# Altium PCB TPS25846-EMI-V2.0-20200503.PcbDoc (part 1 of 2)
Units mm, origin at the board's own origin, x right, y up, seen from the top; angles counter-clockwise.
Board outline 35.01 x 50.01 mm, 4 copper layers (Top Layer, Signal Layer 1, Signal Layer 2, Bottom Layer), stack 2.155 mm thick; 63 components, 30 nets, 189 pads, 82 vias.
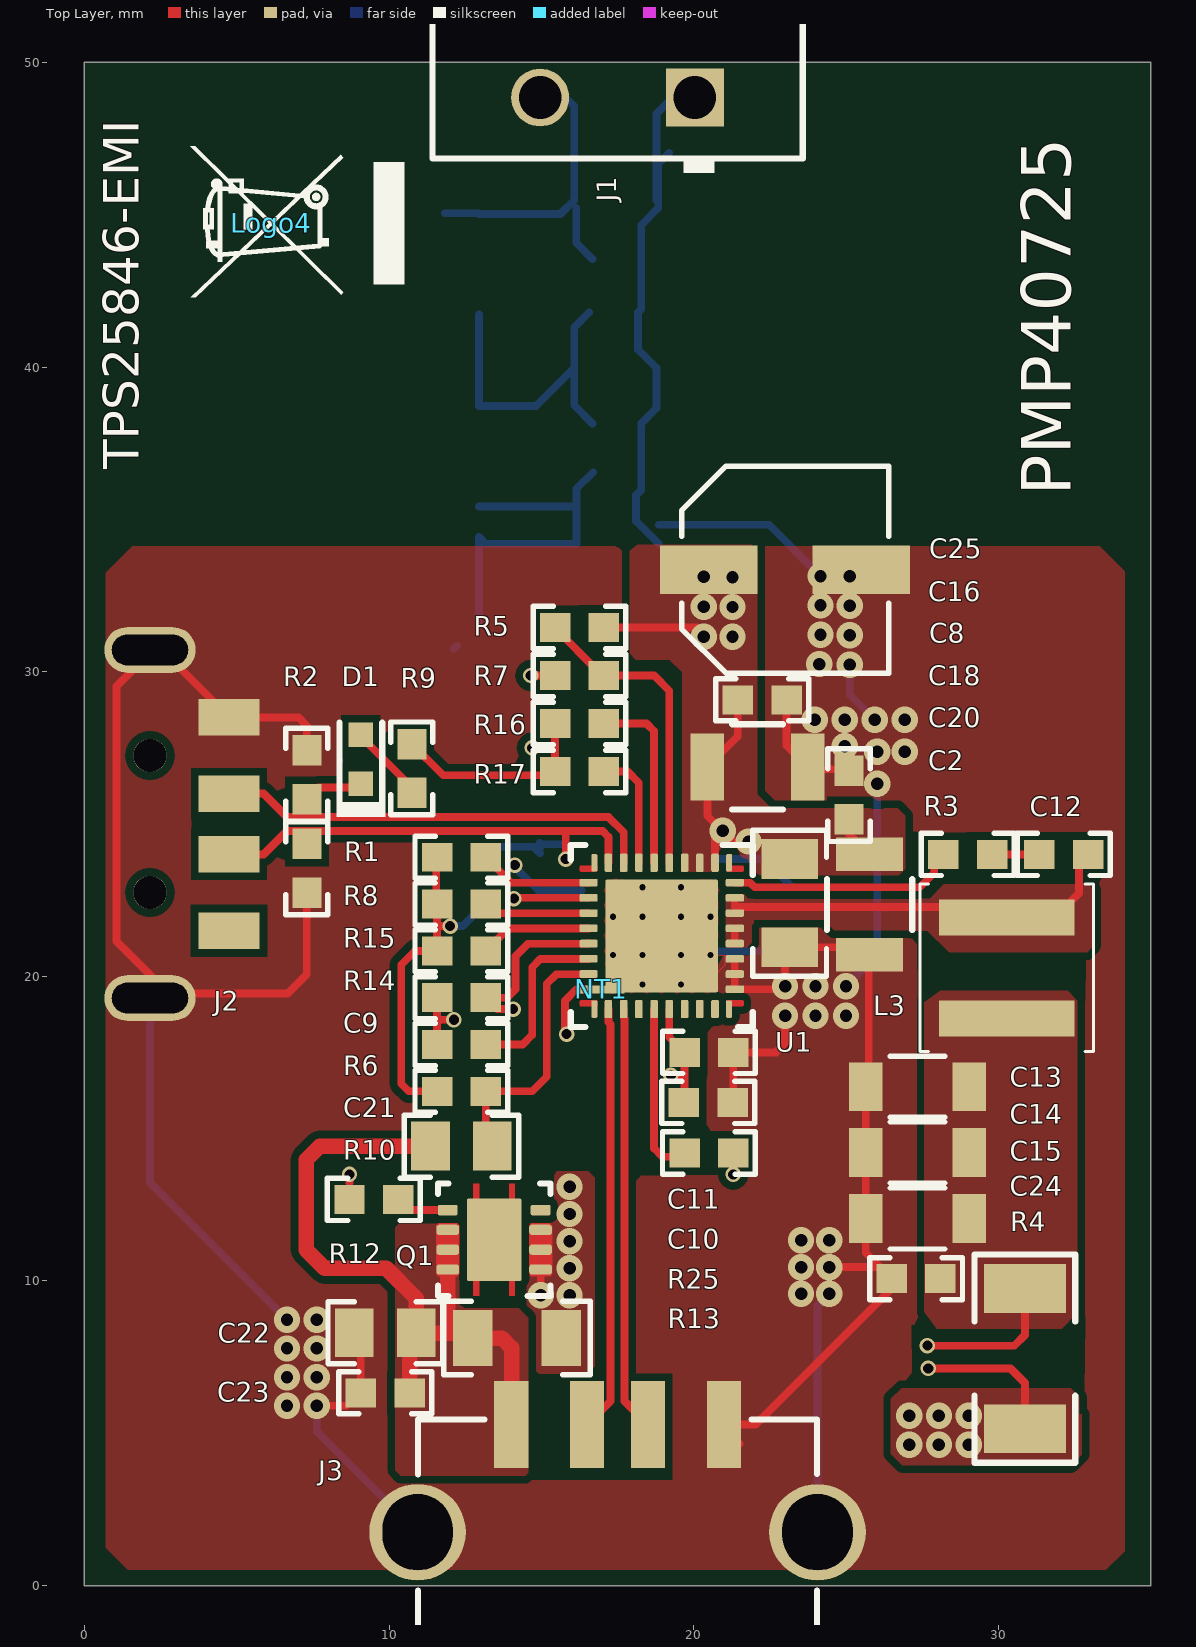
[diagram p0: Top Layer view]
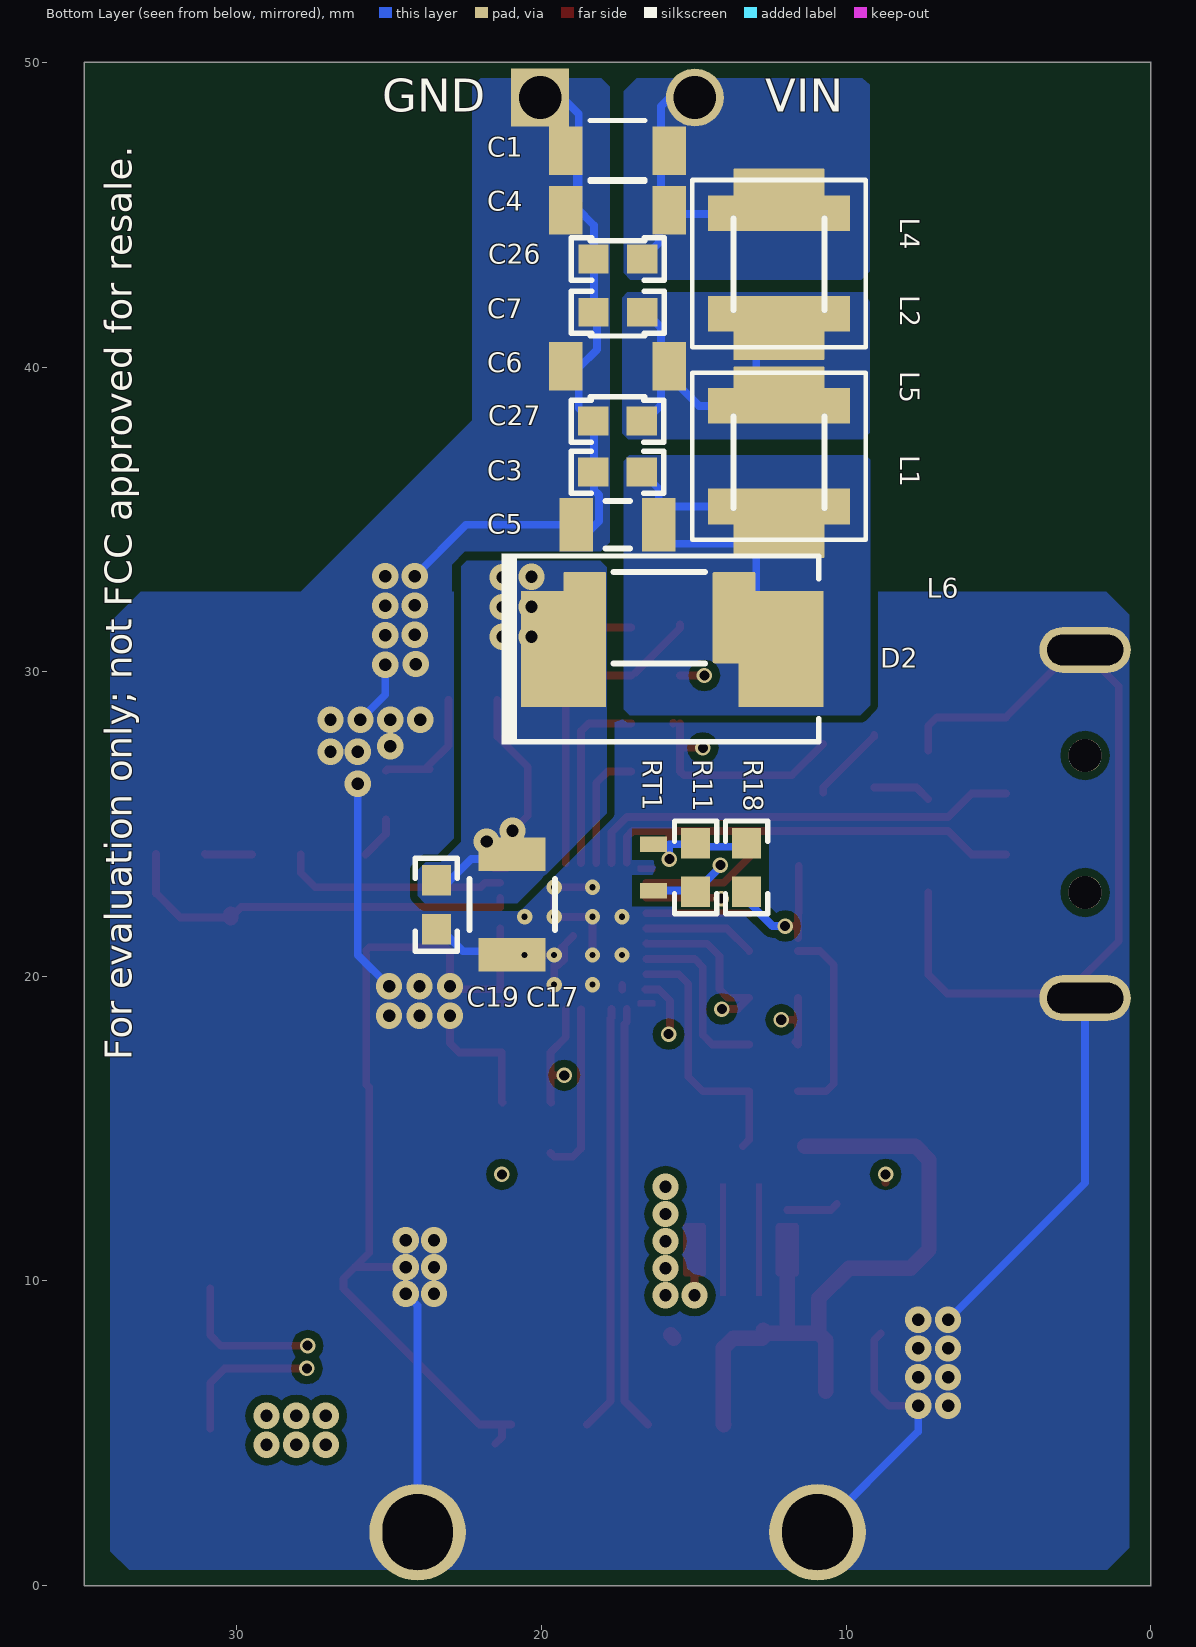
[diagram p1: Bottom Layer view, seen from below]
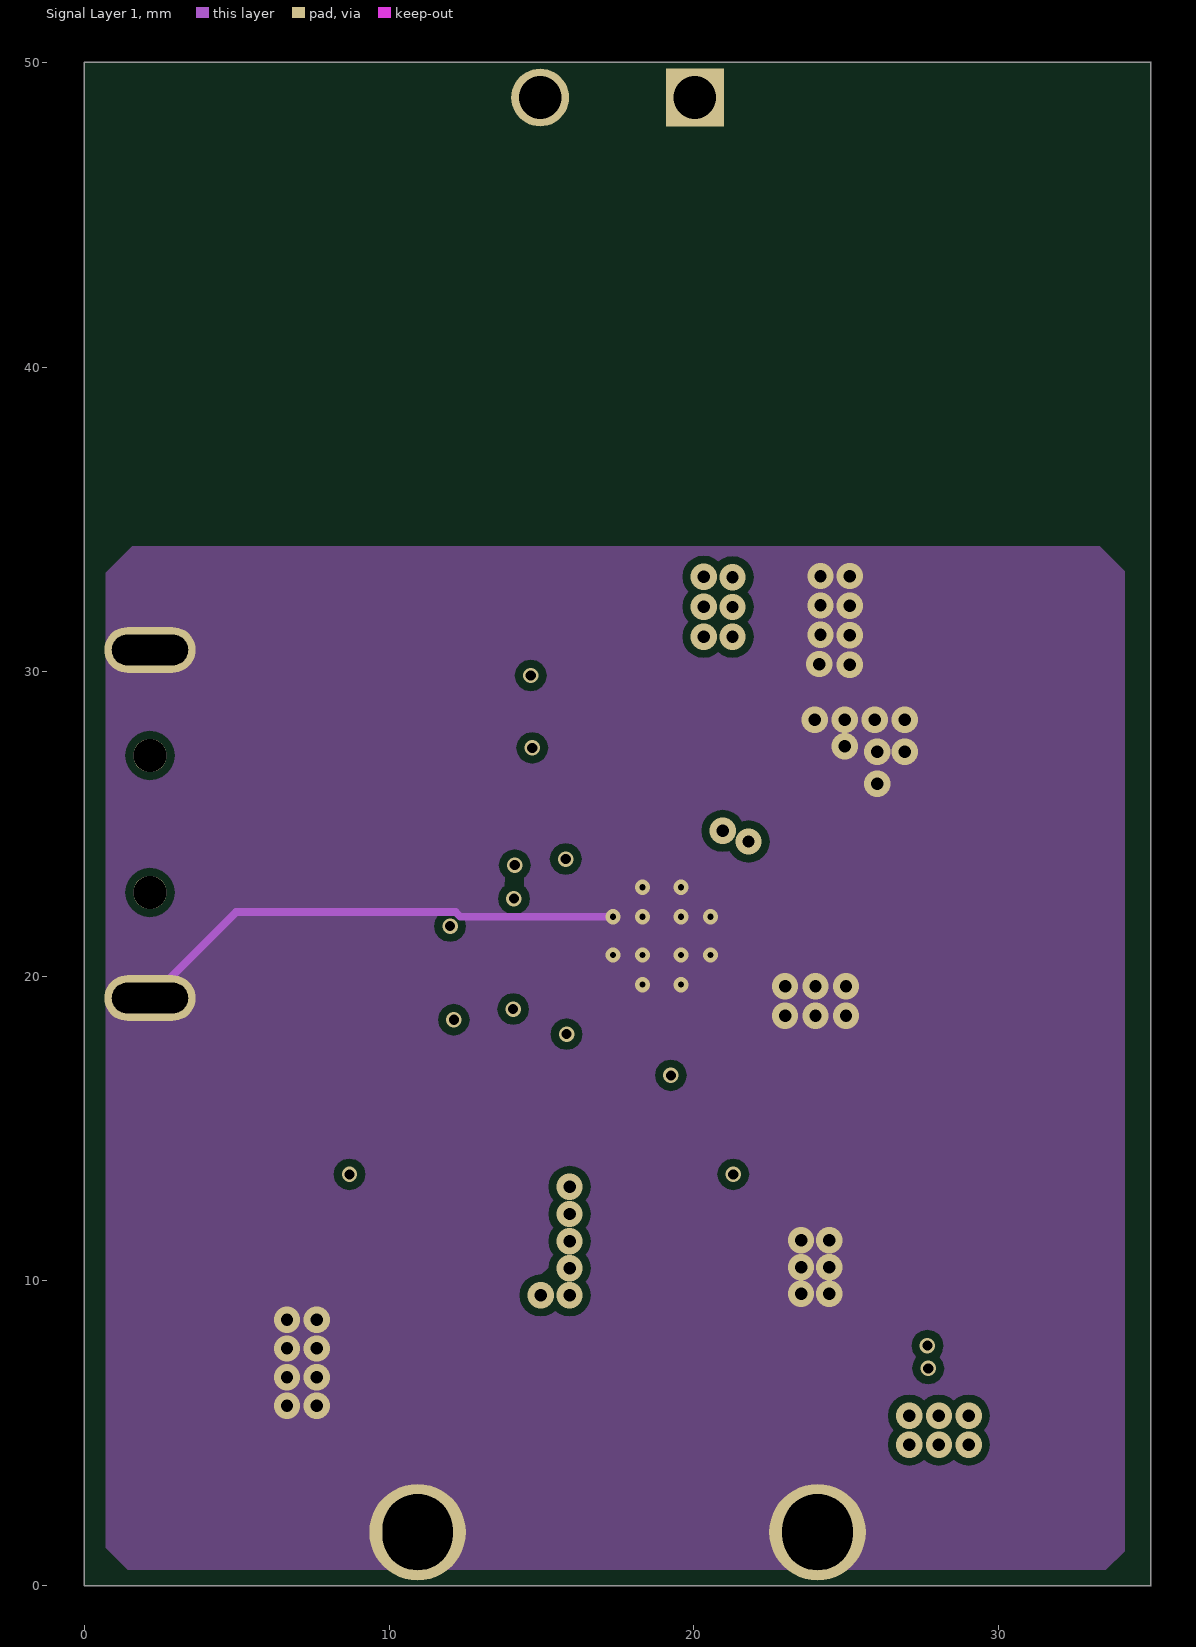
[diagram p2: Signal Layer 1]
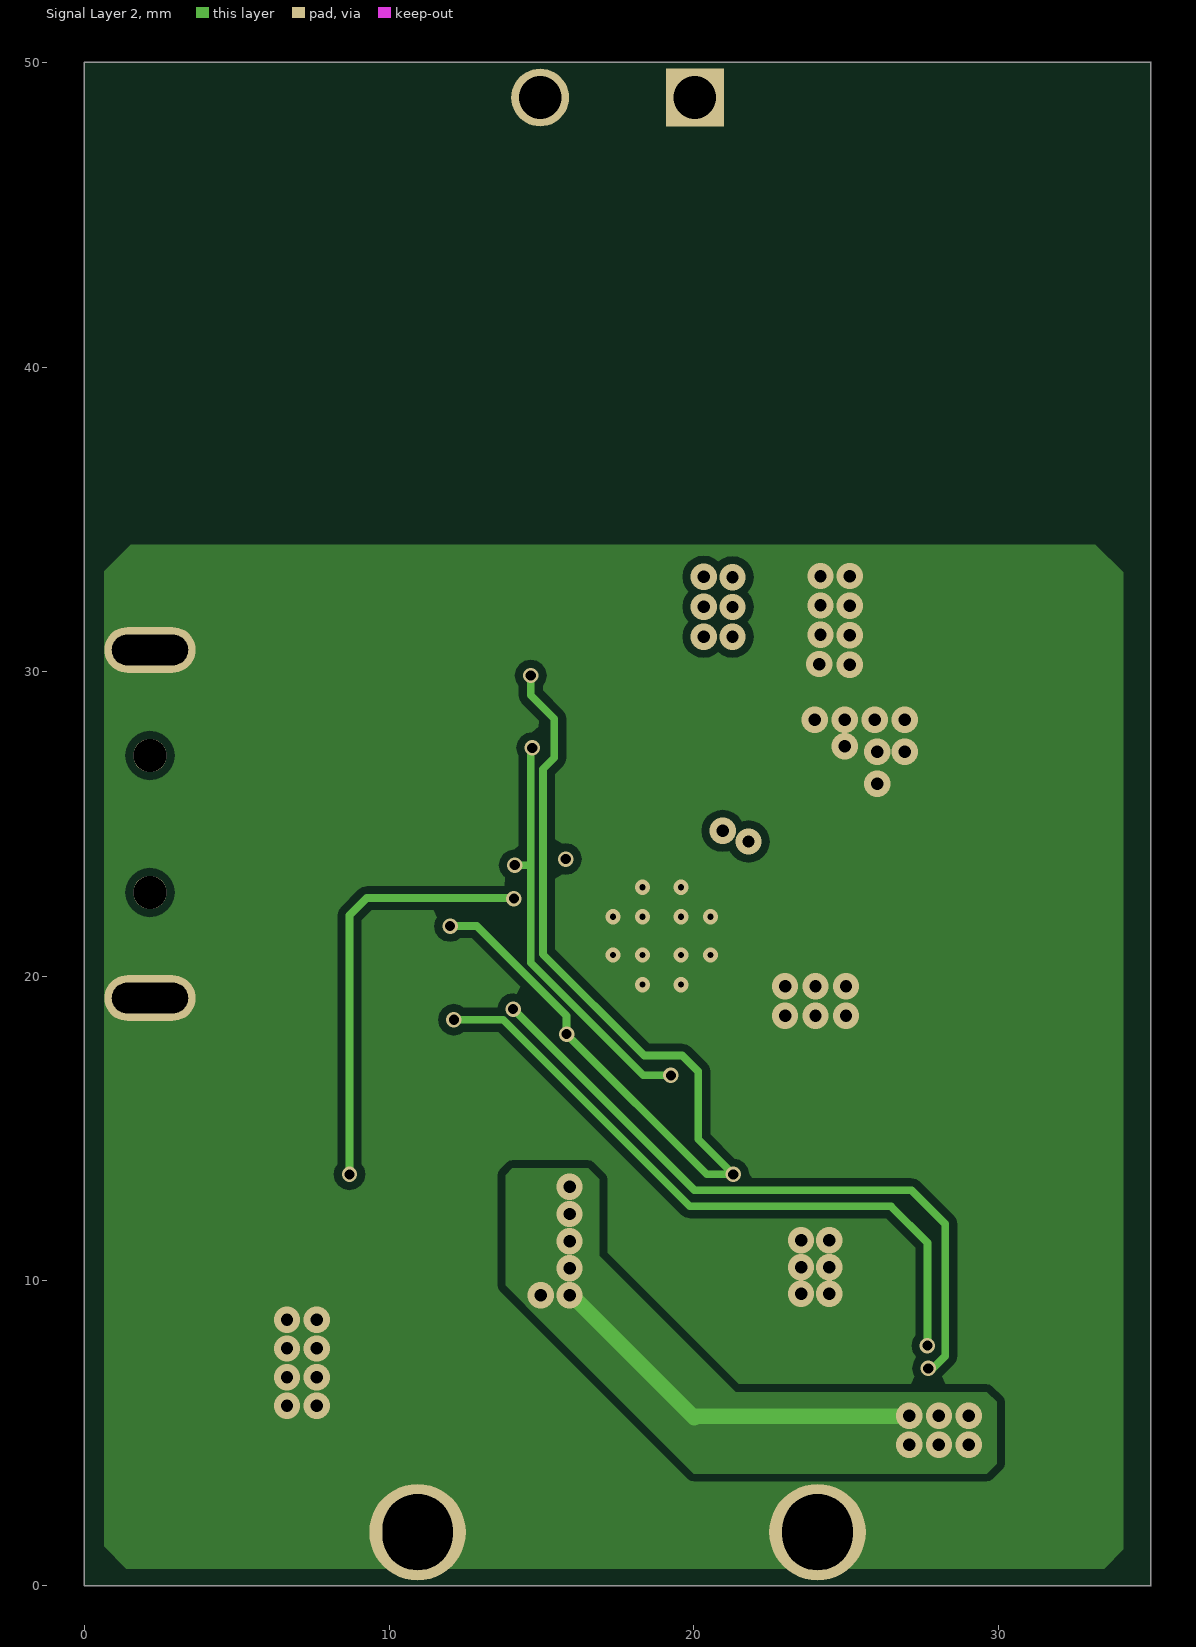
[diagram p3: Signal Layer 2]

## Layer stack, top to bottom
Top Solder: solder mask 0.0102, Solder Resist, Dk 3.5
Top Layer: signal copper 0.0356
Dielectric1: core 1.5037, FR-4, Dk 4.8
Signal Layer 1: signal copper 0.036
Dielectric 2: dielectric 0.254, Dk 4.2
Signal Layer 2: signal copper 0.036
Dielectric 3: dielectric 0.254, Dk 4.2
Bottom Layer: signal copper 0.0356
Bottom Solder: solder mask 0.0102, Solder Resist, Dk 3.5

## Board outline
-0.005,0 ccw(c0,0) 0,-0.005 35,-0.005 ccw(c35,0) 35.005,0 35.005,50 ccw(c35,50) 35,50.005 0,50.005 ccw(c0,50) -0.005,50

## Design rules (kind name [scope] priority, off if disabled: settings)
AcuteAngle [All] p1: minimum=4.50000000000000E+0001 checktracksonly=FALSE
AssemblyTestPointUsage [All] p1: valid=2
BoardOutlineClearance BoardOutlineClearance_1 [ispad and InComponent('J3')] p1: gap=0.508 ignorepadtopadclearanceinfootprint=FALSE
BoardOutlineClearance BoardOutlineClearance_MountingHoles [OnCopper and InComponentClass('Mounting Holes')] p2: gap=0.508 ignorepadtopadclearanceinfootprint=FALSE
BoardOutlineClearance BoardOutlineClearance_Poly [OnCopper and IsPoly] p3: gap=0.508 ignorepadtopadclearanceinfootprint=FALSE
BoardOutlineClearance [OnCopper and Not InComponentClass('Logo') and not InComponentClass('FiducialMark') and not InRegion(1000,500,4000,800) and not InPoly] p4: gap=0.508 ignorepadtopadclearanceinfootprint=FALSE
Clearance Clearance_3 [InComponent('NT1')] p1: gap=0.076 ignorepadtopadclearanceinfootprint=FALSE
Clearance Clearance_2 [isPad or IsArc vs IsKeepOut] p2: gap=0.254 ignorepadtopadclearanceinfootprint=FALSE
Clearance Clearance_1 [InPolygon AND (INNet(VIN) OR InNet('SW')OR InNet('SENS')OR InNet('VBUS1')OR InNet('VBUS2'))] p3: gap=0.254 ignorepadtopadclearanceinfootprint=FALSE
Clearance Clearance_Keepouts [((IsTrack Or IsArc) And Not InPoly) And IsFree and IsKeepOut vs ((IsTrack Or IsArc) And Not InPoly) And IsFree and IsKeepOut] p4: gap=0.254 ignorepadtopadclearanceinfootprint=FALSE
Clearance Clearance_Poly [InPolygon] p5: gap=0.254 ignorepadtopadclearanceinfootprint=FALSE
Clearance [All] p6: gap=0.076 ignorepadtopadclearanceinfootprint=FALSE
ComponentClearance ComponentClearance_1 [InComponent('U1') vs InComponent('NT1')] p1: gap=0 collisioncheckmode=3 verticalgap=0 showdistances=FALSE
ComponentClearance ComponentClearance_MountingHoles_FiducialMarks [InComponentClass('Mounting Holes') vs InComponentClass('FiducialMark')] p2: gap=1.27 collisioncheckmode=3 verticalgap=0.254 showdistances=FALSE
ComponentClearance ComponentClearance_Shunt [InComponentClass('Header') vs InComponentClass('Shunt')] p3: gap=0 collisioncheckmode=3 verticalgap=0 showdistances=FALSE
ComponentClearance ComponentClearance_Logo [InComponentClass('Logo')] p4: gap=1.27 collisioncheckmode=3 verticalgap=0.254 showdistances=FALSE
ComponentClearance ComponentClearance_ScrewToNut [(HasFootprint('NY PMS 440 0025 PH')) vs (HasFootprint('Keystone_1902C'))] p5: gap=0.127 collisioncheckmode=3 verticalgap=0.254 showdistances=FALSE
ComponentClearance ComponentClearance_MountingHoles [InComponentClass('Mounting Holes')] p6: gap=6.35 collisioncheckmode=3 verticalgap=2540 showdistances=FALSE
ComponentClearance ComponentClearance_SmallPassives [HasFootprint('0201*') or HasFootprint('0402*') or HasFootprint('0508') or HasFootprint('0603*') or HasFootprint('0612') or HasFootprint('0805*') or HasFootprint('0815*') or HasFootprint('0830*') or HasFootprint('1206*') or HasFootprint('1210*') or HasFootprint('1808*') or HasFootprint('1812*') or HasFootprint('1825*') or HasFootprint('2010*') or HasFootprint('2220*') or HasFootprint('2225*') or HasFootprint('2512*') or HasFootprint('2728*') or HasFootprint('3518*') vs HasFootprint('0201*') or HasFootprint('0402*') or HasFootprint('0508') or HasFootprint('0603*') or HasFootprint('0612') or HasFootprint('0805*') or HasFootprint('0815*') or HasFootprint('0830*') or HasFootprint('1206*') or HasFootprint('1210*') or HasFootprint('1808*') or HasFootprint('1812*') or HasFootprint('1825*') or HasFootprint('2010*') or HasFootprint('2220*') or HasFootprint('2225*') or HasFootprint('2512*') or HasFootprint('2728*') or HasFootprint('3518*')] p7: gap=0.38 collisioncheckmode=3 verticalgap=0.254 showdistances=FALSE
ComponentClearance ComponentClearance_THtoSMT [IsThruComponent vs IsSMTComponent] p8: gap=0.762 collisioncheckmode=3 verticalgap=0.762 showdistances=FALSE
ComponentClearance ComponentClearance_THtoTH [IsThruComponent vs IsThruComponent] p9: gap=0.762 collisioncheckmode=3 verticalgap=0.762 showdistances=FALSE
ComponentClearance [All] p10 off: gap=0.762 collisioncheckmode=3 verticalgap=0.254 showdistances=FALSE
DiffPairsRouting [InDifferentialPairClass('All Differential Pairs')] p1: maxlimit=0.254 minlimit=0.127 mostfreqgap=0.203 toplayer_minwidth=0.127 toplayer_maxwidth=0.254 toplayer_prefwidth=0.203 midlayer1_minwidth=0.127 midlayer1_maxwidth=0.254 midlayer1_prefwidth=0.203 midlayer2_minwidth=0.127 midlayer2_maxwidth=0.254 midlayer2_prefwidth=0.203 bottomlayer_minwidth=0.127 bottomlayer_maxwidth=0.254 bottomlayer_prefwidth=0.203 maxuncoupledlength=254
FabricationTestPointUsage TestPointUsage [All] p1: valid=2 allowmultiple=FALSE
FabricationTestpoint Testpoint [All] p1: side=3 testpointundercomponent=TRUE minsize=1.016 maxsize=2.54 preferedsize=1.524 minholesize=0 maxholesize=1.016 preferedholesize=0.813 testpointgrid=0.025 allowsidetop=TRUE allowsidebottom=TRUE usegrid=TRUE gridtolerance=0
FanoutControl Fanout_LCC [IsLCC] p1: bgadir=Out bgaviamode=Centered fanoutstyle=Auto fanoutdirection=Alternating viagrid=0.025 // Fanout_LCC (Default Rule)
FanoutControl Fanout_BGA [IsBGA] p2: bgadir=Out bgaviamode=Centered fanoutstyle=Auto fanoutdirection=Alternating viagrid=0.025 // Fanout_BGA (Default Rule)
FanoutControl Fanout_Default [All] p4: bgadir=Out bgaviamode=Centered fanoutstyle=Auto fanoutdirection=Alternating viagrid=0.025 // Fanout_Default (Default Rule)
FanoutControl Fanout_Small [(CompPinCount < 5)] p5: bgadir=Out bgaviamode=Centered fanoutstyle=Auto fanoutdirection=OutThenIn viagrid=0.025 // Fanout_Small (Default Rule)
HoleSize [All] p1: absolutevalues=TRUE maxlimit=6.375 minlimit=0.152 maxpercent=80.000 minpercent=20.000
HoleToHoleClearance [All] p1: gap=0.152 allowstackedmicrovias=TRUE
MinimumAnnularRing MinimumAnnularRing_ThermalPadVias [IsPad] p1: minimumring=0.051
MinimumAnnularRing [All] p2: minimumring=0.076
MinimumSolderMaskSliver MinimumSolderMaskSliver_Logo [InComponentClass('Logo') vs InComponentClass('Logo')] p1: minsoldermaskwidth=0.025
MinimumSolderMaskSliver [All] p2: minsoldermaskwidth=0
PlaneConnect [All] p1: planeconnectstyle=Direct reliefexpansion=0.254 reliefentries=4 reliefconductorwidth=0.254 reliefairgap=0.254
PolygonConnect [All] p1: connectstyle=Direct reliefconductorwidth=0.254 reliefentries=4 polygonreliefangle="90 Angle" airgapwidth=0.254
RoutingVias ThermalPadVias [IsVia and InAnyComponent] p1: holewidth=0.2 width=0.33 viastyle="Through Hole" minholewidth=0.198 minwidth=0.33 maxholewidth=0.33 maxwidth=0.381
RoutingVias [All] p2: holewidth=0.254 width=0.33 viastyle="Through Hole" minholewidth=0.152 minwidth=0.254 maxholewidth=0.33 maxwidth=0.508
ShortCircuit ShortCircuit_1 [ispad and InComponent('U1')] p1: allowed=TRUE
ShortCircuit [All] p2: allowed=FALSE
SilkToBoardRegionClearance [Not ((IsComment or IsDesignator) And (Hide <> 'False')) and not InRegion(1000,500,4000,800)] p1:
SilkToSilkClearance SilkToSilkClearance_Pb-FreeLogo [(HasFootprint('Pb-Free_Overlay_Medium') OR HasFootprint('Pb-Free_Overlay_Small')) vs (HasFootprint('Pb-Free_Overlay_Medium') OR HasFootprint('Pb-Free_Overlay_Small'))] p1: silktosilkclearance=0
SilkToSilkClearance [All] p2: silktosilkclearance=0
SilkToSolderMaskClearance [IsPad] p1: minsilkscreentomaskgap=0 clearancetoexposedcopper=TRUE
SilkToSolderMaskClearance SilkToComponentPadClearance [(IsPad or IsFill or IsRegion) and InAnycomponent] p2: minsilkscreentomaskgap=0 clearancetoexposedcopper=TRUE
SolderMaskExpansion [All] p1: expansion=0.05
Width [All] p1: maxlimit=2.54 minlimit=0.152 preferedwidth=0.254 midlayer1_minwidth=0.178 midlayer2_minwidth=0.178 bottomlayer_minwidth=0.178 minimp=50.000000 maximp=50.000000 favimp=50.000000 checkconnectedcopper=TRUE
13 further rules are at their usual default settings.

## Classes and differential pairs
component class TPS25846-EMI-V2.0: !PCB Logo3 Logo4
differential pair DATA_OUT: +DATA_OUT_P -DATA_OUT_N
differential pair DATA_IN: +DATA_IN_P -DATA_IN_N

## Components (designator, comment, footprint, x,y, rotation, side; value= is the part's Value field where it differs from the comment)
C1 "CGA5L1X7R1H106K160AC" 1206_190 17.5,47.1 r0 bottom value=10uF
C2 "UMJ325KB7106MMHP" 1210_280 25.775,22.35 r270 top value=10uF
C3 "C0603X332K5RACTU" 0603 17.5,36.55 r0 bottom value=3300pF
C4 "UMJ316AB7225KLHT" 1206_180 17.5,45.15 r0 bottom value=2.2uF
C5 "GRM31CR71H475KA12L" 1206_180L 17.5,34.825 r0 bottom value=4.7uF
C6 "UMJ316AB7225KLHT" 1206_180 17.5,40.025 r0 bottom value=2.2uF
C7 "C0603X332K5RACTU" 0603 17.49,41.8 r0 bottom value=3300pF
C8 "GRM1885C1H222JA01D" 0603 22.25,29.075 r0 top value=2200pF
C9 "C0603C104K5RACAUTO" 0603 12.375,19.299 r180 top value=0.1uF
C10 "885012106018" 0603 20.475,15.858 r0 top value=2.2uF
C11 "C0603C104K5RACAUTO" 0603 20.5,17.5 r0 top value=0.1uF
C12 "C0603C104K5RACAUTO" 0603 32.15,24 r0 top value=0.1uF
C13 "GCM31CR71A226KE02" 1206_180 27.35,16.375 r180 top value=22uF
C14 "GCM31CR71A226KE02" 1206_180 27.35,14.212 r180 top value=22uF
C15 "GCM31CR71A226KE02" 1206_180 27.35,12.05 r180 top value=22uF
C16 "C0603C104K5RACAUTO" 0603 25.1,25.95 r90 top value=0.1uF
C17 "UMJ325KB7106MMHP" 1210_280 20.959,22.35 r270 bottom value=10uF
C18 "UMJ325KB7106MMHP" 1210_280 22.1,26.875 r0 top value=10uF
C19 "C0603C104K5RACAUTO" 0603 23.45,22.35 r270 bottom value=0.1uF
C20 "C1206C104M5RACTU" 1206 23.15,22.4 r270 top value=0.1uF
C21 "CL10B224KO8VPNC" 0603 12.375,16.225 r180 top value=0.22uF
C22 "08055C105KAT2A" 0805_HV 9.875,8.3 r180 top value=1uF
C23 "C0603C104K5RACAUTO" 0603 9.875,6.325 r180 top value=0.1uF
C24 "GRM1885C1H222JA01D" 0603 27.3,10.075 r180 top value=2200pF
C25 "EEE-FK1H220P" SM_RADIAL_D 23,33.35 r0 top value=22uF
C26 "GRM188R71H222KA01D" 0603 17.49,43.55 r0 bottom value=2200pF
C27 "GRM188R71H222KA01D" 0603 17.5,38.225 r0 bottom value=2200pF
D1 "150060RS75000" WL-SMCW_RED 9.075,27.125 r90 top value=NC
D2 "B540C-13-F" SMC 15.7,30.75 r180 bottom value=40V
J1 "1757242" PHOENIX_1757242 17.5,52.85 r180 top locked
J2 "48037-1000" CONN_USB-A-48037-1000 2.5,25 r180 top locked
J3 "896-43-004-00-000000" CONN_USB_896-43-004-00-000000 17.5,3.517 r0 top locked
L1 "74279252" 1812_170_HighSpeed 12.2,36.875 r270 bottom value="880 ohm"
L2 "NC" 1812_170_HighSpeed 12.2,43.375 r270 bottom value="880 ohm"
L3 "XAL5050-822MEB" XAL5050 30.275,20.275 r270 top value=8.2uH
L4 "XAL5030-102MEB" XAL5030 12.2,43.4 r270 bottom value=1uH
L5 "XAL5030-102MEB" XAL5030 12.2,37.075 r270 bottom value=1uH
L6 "NC" 1812_170_HighSpeed 16.125,31.775 r0 bottom value="880 ohm"
Logo3 "FCC disclaimer" FCC_disclaimer -9.05,95.425 r90 top
Logo4 "WEEE logo" WEEE_Minimum 6.125,44.721 r90 top
NT1 "Net-Tie" Net-Tie_10milWide_30milLong 16.966,19.57 r180 top net-tie
Q1 "CSD85312Q3E" DPA0008A 13.45,11.35 r180 top value=20V
R1 "CRCW060349K9FKEA" 0603 12.375,23.907 r0 top value=49.9k
R2 "CRCW060315K0JNEA" 0603 7.3,26.616 r270 top value=15k
R3 "MCT06030C2008FP500" 0603 29,24 r0 top value=2.00
R4 "WSL2010R0150FEA" 2010 30.875,7.45 r270 top value=0.015
R5 "CRCW060320K0JNEA" 0603 16.25,31.45 r0 top value=20k
R6 "CRCW0603301RFKEA" 0603 12.375,17.762 r180 top value=301
R7 "CR0603-FX-4991ELF" 0603 16.25,29.874 r0 top value=4.99k
R8 "CRCW060315K0JNEA" 0603 7.3,23.55 r90 top value=15k
R9 "CRCW060310K0JNEA" 0603 10.747,26.825 r90 top value=10k
R10 "ERJ-6GEYJ101V" 0805_HV 12.375,14.425 r180 top value=100
R11 "CRCW06031K00FKEA" 0603 14.94,23.575 r270 bottom value=1.00k
R12 "RMCF0603ZT0R00" 0603 9.5,12.675 r0 top value=0
R13 "RC1206JR-070RL" 1206 14.2,8.125 r0 top value=0
R14 "CRCW06035K62FKEA" 0603 12.375,20.834 r0 top value=5.62k
R15 "CR0603-FX-4991ELF" 0603 12.375,22.372 r180 top value=4.99k
R16 "CRCW0603100KFKEA" 0603 16.25,28.301 r180 top value=100k
R17 "CRCW0603100KFKEA" 0603 16.25,26.725 r180 top value=100k
R18 "CRCW060339K2FKEA" 0603 13.264,23.575 r90 bottom value=39.2k
R25 "CRCW06035K10JNEA" 0603 20.5,14.2 r180 top value=5.1k
RT1 "NCP18WM474J03RB" 0603S 16.325,23.575 r270 bottom value=NC
U1 "TPS25840QWRHBTQ1" RHB0032R 18.95,21.325 r270 top

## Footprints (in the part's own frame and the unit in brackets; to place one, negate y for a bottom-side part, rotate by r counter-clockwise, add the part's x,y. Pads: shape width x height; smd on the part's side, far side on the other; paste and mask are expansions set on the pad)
0603 [mm] "0603 from SM-752 data"
  rect 1x0.95 smd: 1(-0.8,0) 2(0.8,0)
  silkscreen extent -1.52,-0.69 1.52,0.69, body extent -0.87,-0.47 0.87,0.47, height 1
0603S [mil]
  rect 20x35 smd: 1(-30,0) 2(30,0)
  body extent -34,-19 34,19, height 39
0805_HV [mil] "0805 with 30mil clearance between pads"
  rect 50x63 smd: 1(-40,0) 2(40,0)
  silkscreen extent -74,-40 74,40, body extent -43,-29 43,29, height 57
1206 [mm] "1206 from SM-752 data"
  rect 1.3x1.85 smd: 1(-1.45,0) 2(1.45,0)
  silkscreen extent -2.4,-1.21 2.4,1.21, body extent -1.7,-0.9 1.7,0.9, height 1.35
1206_180 [mm] "1206_180"
  rect 1.1x1.6 smd: 1(-1.7,0) 2(1.7,0)
  silkscreen extent -0.9,-1 0.9,1, body extent -1.75,-0.95 1.75,0.95, height 1.8
1206_180L [mm] "1206_180"
  rect 1.1x1.75 smd: 1(-1.35,0) 2(1.35,0)
  silkscreen extent -0.4,-0.77 0.4,0.77, body extent -1.75,-0.95 1.75,0.95, height 1.8
1206_190 [mm] "1206_190"
  rect 1.1x1.6 smd: 1(-1.7,0) 2(1.7,0)
  silkscreen extent -0.9,-1 0.9,1, body extent -1.75,-0.95 1.75,0.95, height 1.9
1210_280 [mm] "SMD, 2-Leads, Body 3.6x2.8mm, Height 2.8mm"
  rect 1.1x2.2 smd: 1(-1.65,0) 2(1.65,0)
  silkscreen extent -0.84,-1.4 0.84,1.4, body extent -1.8,-1.4 1.8,1.4, height 2.8
1812_170_HighSpeed [mm] "Wurth recommended land pattern"
  rrect7% 1.4x3 smd: 1(-2.45,0) 2(2.45,0)
  silkscreen extent -1.5,-1.5 1.5,1.5, body extent -2.25,-1.6 2.25,1.6, height 1.51
2010 [mm] "Chip Capacitor, Body 5.08x2.54mm, IPC Medium Density"
  rect 1.6x2.7 smd: 1(-2.3,0) 2(2.3,0)
  silkscreen extent -3.42,-1.65 3.42,1.65, body extent -2.73,-1.45 2.73,1.45, height 1.66
CONN_USB-A-48037-1000 [mm] "Molex"
  rect 2x1.2 smd: 1(-2.25,3.5) 2(-2.25,1) 3(-2.25,-1) 4(-2.25,-3.5)
  oval 3x1.5 hole 1 slot 2.5 at 0 deg: 5(0.35,5.715) 6(0.35,-5.715)
  round 1.092 hole 1.092 unplated: 7(0.35,2.248) 8(0.35,-2.248)
  body extent -3.13,-6.35 18.15,6.35, height 3.09
CONN_USB_896-43-004-00-000000 [mm] "MILLMAX"
  rect 1.12x2.87 smd: 1(-3.49,1.768) 2(-1,1.768) 3(1,1.768) 4(3.49,1.768)
  round 3.17 hole 2.3 slot 2.5 at 90 deg: 5(-6.565,-1.767) 6(6.565,-1.767)
  silkscreen extent -6.55,-10.54 6.55,1.93, body extent -6.55,-12.07 6.55,1.92, height 6.99
DPA0008A [mm] "SON, 8-Leads, Body 3.3x3.3mm, Pitch 0.65mm"
  rrect59% 0.75x0.34 smd paste-0.2 mask-0.2: 1(-1.525,0.975) 2(-1.525,0.325) 3(-1.525,-0.325) 6(1.525,-0.325) 7(1.525,0.325) 8(1.525,0.975)
  rrect29% 0.65x0.34 smd: 4(-1.525,-0.975) 5(1.525,-0.975)
  rrect50% 0.2x0.3 on Top Paste: 9(-0.59,1.7) 9(-0.59,-1.7) 9(0.59,1.7) 9(0.59,-1.7)
  rrect8% 1.63x1.19 on Top Paste: 9(0,0.695) 9(0,-0.695)
  rrect6% 1.8x2.7 smd paste-1: 9(0,0)
  Top Layer region: 0.49,-1.85 0.69,-1.85 0.69,1.85 0.49,1.85
  Top Layer region: -0.49,1.85 -0.69,1.85 -0.69,-1.85 -0.49,-1.85
  Top Layer region: -1.9,-0.44 -1.9,1.1 -1.892,1.138 -1.871,1.171 -1.838,1.192 -1.8,1.2 -1.8,1.2 -1.25,1.2 -1.212,1.192 -1.179,1.171 -1.158,1.138 -1.15,1.1 -1.15,1.1 -1.15,-0.44 -1.158,-0.478 -1.179,-0.511 -1.212,-0.532 -1.25,-0.54 -1.25,-0.54 -1.8,-0.54 -1.838,-0.532 -1.871,-0.511 -1.892,-0.478 -1.9,-0.44
  Top Layer region: 1.9,-0.44 1.9,1.1 1.892,1.138 1.871,1.171 1.838,1.192 1.8,1.2 1.8,1.2 1.25,1.2 1.212,1.192 1.179,1.171 1.158,1.138 1.15,1.1 1.15,1.1 1.15,-0.44 1.158,-0.478 1.179,-0.511 1.212,-0.532 1.25,-0.54 1.25,-0.54 1.8,-0.54 1.838,-0.532 1.871,-0.511 1.892,-0.478 1.9,-0.44
  silkscreen extent -1.85,-1.85 1.85,1.85, body extent -1.7,-1.7 1.7,1.7, height 1.01
FCC_disclaimer [mm]
Net-Tie_10milWide_30milLong [mil] "10mil net tie, no solder mask opening, no solder paste"
  rect 30x10 smd paste-5 mask-5: 1(-15,0) 2(15,0)
PHOENIX_1757242 [mm] "Header, 5.08 mm, 2x1, R/A, TH"
  rect 1.9x1.9 hole 1.4: 1(-2.54,4)
  round 1.9 hole 1.4: 2(2.54,4)
  silkscreen extent -6.08,-6 6.08,6.47, body extent -6.05,-5.93 6.1,6.08, height 8.6
RHB0032R [mm] "QFN, 32-Leads, Body 5x5mm, Pitch 0.5mm, Thermal Pad 3.7x3.7mm"
  rrect40% 0.6x0.25 smd: 1(-2.4,1.75) 2(-2.4,1.25) 3(-2.4,0.75) 4(-2.4,0.25) 5(-2.4,-0.25) 6(-2.4,-0.75) 7(-2.4,-1.25) 8(-2.4,-1.75) 17(2.4,-1.75) 18(2.4,-1.25) 19(2.4,-0.75) 20(2.4,-0.25) 21(2.4,0.25) 22(2.4,0.75) 23(2.4,1.25) 24(2.4,1.75)
  rrect40% 0.25x0.6 smd: 9(-1.75,-2.4) 10(-1.25,-2.4) 11(-0.75,-2.4) 12(-0.25,-2.4) 13(0.25,-2.4) 14(0.75,-2.4) 15(1.25,-2.4) 16(1.75,-2.4) 25(1.75,2.4) 26(1.25,2.4) 27(0.75,2.4) 28(0.25,2.4) 29(-0.25,2.4) 30(-0.75,2.4) 31(-1.25,2.4) 32(-1.75,2.4)
  rrect9% 1.06x1.06 on Top Paste: 33(-1.26,1.26) 33(-1.26,0) 33(-1.26,-1.26) 33(0,1.26) 33(0,0) 33(0,-1.26) 33(1.26,1.26) 33(1.26,0) 33(1.26,-1.26)
  rrect3% 3.7x3.7 smd paste-2: 33(0,0)
  rrect50% 0.575x0.2 smd: A1(-2.4,2.213) A2(-2.4,-2.213) A3(2.4,-2.213) A4(2.4,2.213)
  Top Layer region: 2.113,2.638 2.113,2.163 2.116,2.143 2.127,2.127 2.143,2.116 2.163,2.113 2.163,2.113 2.262,2.113 2.282,2.116 2.298,2.127 2.309,2.143 2.312,2.163 2.312,2.163 2.312,2.638 2.309,2.657 2.298,2.673 2.282,2.684 2.262,2.688 2.262,2.688 2.163,2.688 2.143,2.684 2.127,2.673 2.116,2.657 2.113,2.638
  Top Layer region: -2.113,2.638 -2.113,2.163 -2.116,2.143 -2.127,2.127 -2.143,2.116 -2.163,2.113 -2.163,2.113 -2.262,2.113 -2.282,2.116 -2.298,2.127 -2.309,2.143 -2.312,2.163 -2.312,2.163 -2.312,2.638 -2.309,2.657 -2.298,2.673 -2.282,2.684 -2.262,2.688 -2.262,2.688 -2.163,2.688 -2.143,2.684 -2.127,2.673 -2.116,2.657 -2.113,2.638
  Top Layer region: -2.113,-2.638 -2.113,-2.163 -2.116,-2.143 -2.127,-2.127 -2.143,-2.116 -2.163,-2.113 -2.163,-2.113 -2.262,-2.113 -2.282,-2.116 -2.298,-2.127 -2.309,-2.143 -2.312,-2.163 -2.312,-2.163 -2.312,-2.638 -2.309,-2.657 -2.298,-2.673 -2.282,-2.684 -2.262,-2.688 -2.262,-2.688 -2.163,-2.688 -2.143,-2.684 -2.127,-2.673 -2.116,-2.657 -2.113,-2.638
  Top Layer region: 2.113,-2.638 2.113,-2.163 2.116,-2.143 2.127,-2.127 2.143,-2.116 2.163,-2.113 2.163,-2.113 2.262,-2.113 2.282,-2.116 2.298,-2.127 2.309,-2.143 2.312,-2.163 2.312,-2.163 2.312,-2.638 2.309,-2.657 2.298,-2.673 2.282,-2.684 2.262,-2.688 2.262,-2.688 2.163,-2.688 2.143,-2.684 2.127,-2.673 2.116,-2.657 2.113,-2.638
  silkscreen extent -2.99,-2.99 2.99,2.99, body extent -2.5,-2.5 2.5,2.5, height 1
SM_RADIAL_D [mm] "6.3 x 5.8mm:  Panasonic D"
  rect 3.2x1.6 smd: 1(-2.5,0) 2(2.5,0)
  silkscreen extent -3.4,-3.4 3.4,3.4, body extent -3.4,-3.4 3.4,3.4, height 6.1
SMC [mil] "Molded Diode, 2-Leads, Body 6.9x5.8mm, IPC Medium Density, based on OnSemi component dimensions and land patterns"
  rect 110x150 smd: 1(-140.49,0) 2(140.49,0)
  silkscreen extent -221,-123 189,124, body extent -156,-116 156,116, height 91
WEEE_Minimum [mm] "WEEElie bin"
  silkscreen extent -2.42,-4.38 2.52,2.65
WL-SMCW_RED [mm] "WURTH"
  rect 0.8x0.8 smd: 1(-0.8,0) 2(0.8,0)
  silkscreen extent -1.9,-0.8 1.2,0.8, body extent -0.85,-0.45 0.85,0.45, height 0.8
XAL5030 [mil] "Coilcraft XAL5030 12/12/11"
  rect 46x183 smd: 1(-65,0) 2(65,0)
  silkscreen extent -108,-112 108,112, body extent -108,-112 108,112, height 122
XAL5050 [mm] "CoilCraft XAL5050 5.28 x 5.48 x 5.1 mm"
  rect 1.18x4.44 smd: 1(-1.655,0) 2(1.655,0)
  silkscreen extent -2.75,-2.85 2.75,2.85, body extent -2.74,-2.84 2.74,2.84, height 5.1

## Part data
C1: library part CMP-0085950-1, "CAP, CERM, 10 µF, 50 V,+/- 10%, X7R, AEC-Q200 Grade 1, 1206", Cap_Case=1206, Manufacturer=TDK, TempCo=X7R, Tolerance_%=10%, Value2=50V, ValueDisplayed=10µF
C2 C18: library part CMP-0082302-1, "CAP, CERM, 10 µF, 50 V,+/- 20%, X7R, AEC-Q200 Grade 1, 1210", Cap_Case=1210, Manufacturer="Taiyo Yuden", Supplier Part Number 1=587-6027-1-ND, TempCo=X7R, Tolerance_%=20%, Value2=50V, ValueDisplayed=10µF
C3 C7: library part CMP-0006985-4, "CAP, CERM, 3300 pF, 50 V, +/- 10%, X7R, 0603", Cap_Case=0603, Manufacturer=Kemet, Supplier Part Number 1=399-5339-1-ND, TempCo=X7R, Tolerance_%=10%, Value1=Unknown, Value2=50V, ValueDisplayed=3300pF
C4 C6: library part CMP-0080745-1, "CAP, CERM, 2.2 µF, 50 V,+/- 10%, X7R, AEC-Q200 Grade 1, 1206", Cap_Case=1206, Manufacturer="Taiyo Yuden", Supplier Part Number 1=587-4271-1-ND, TempCo=X7R, Tolerance_%=10%, Value2=50V, ValueDisplayed=2.2µF
C5: library part CMP-0008969-2, "CAP, CERM, 4.7 uF, 50 V, +/- 10%, X7R, 1206", Cap_Case=2220, Manufacturer=MuRata, Supplier Part Number 1=24R6347, TempCo=X7R, Tolerance_%=10%, Value1=Unknown, Value2=50V, ValueDisplayed=NC
C8: library part CMP-0007198-4, "CAP, CERM, 2200 pF, 50 V, +/- 5%, C0G/NP0, 0603", Cap_Case=0603, Manufacturer=MuRata, Supplier Part Number 1=490-1459-1-ND, TempCo=C0G/NP0, Tolerance_%=5%, Value1=Unknown, Value2=50V, ValueDisplayed=NC
C9 C11 C12 C16 C23: library part CMP-0079602-1, "CAP, CERM, 0.1 µF, 50 V,+/- 10%, X7R, AEC-Q200 Grade 1, 0603", Cap_Case=0603, Manufacturer=Kemet, Supplier Part Number 1=399-6856-1-ND, TempCo=X7R, Tolerance_%=10%, Value2=50V, ValueDisplayed=0.1µF
C10: library part CMP-0006825-5, "CAP, CERM, 2.2 uF, 16 V, +/- 20%, X5R, 0603", Cap_Case=0603, Manufacturer="Wurth Elektronik", Supplier Part Number 1=732-7915-1-ND, TempCo=X5R, Tolerance_%=20%, Value1=Unknown, Value2=16V, ValueDisplayed=2.2uF
C13 C14 C15: library part CMP-0008811-2, "CAP, CERM, 22 uF, 10 V, +/- 10%, X7R, AEC-Q200 Grade 1, 1206", Cap_Case=1206, Manufacturer=MuRata, TempCo=X7R, Tolerance_%=10%, Value1=Unknown, Value2=10V, ValueDisplayed=22uF
C17: library part CMP-0082302-1, "CAP, CERM, 10 µF, 50 V,+/- 20%, X7R, AEC-Q200 Grade 1, 1210", Cap_Case=1210, Manufacturer="Taiyo Yuden", Supplier Part Number 1=587-6027-1-ND, TempCo=X7R, Tolerance_%=20%, Value2=50V, ValueDisplayed=NC
C19: library part CMP-0079602-1, "CAP, CERM, 0.1 µF, 50 V,+/- 10%, X7R, AEC-Q200 Grade 1, 0603", Cap_Case=0603, Manufacturer=Kemet, Supplier Part Number 1=399-6856-1-ND, TempCo=X7R, Tolerance_%=10%, Value2=50V, ValueDisplayed=NC
C20: library part CMP-0008587-2, "CAP, CERM, 0.1 uF, 50 V, +/- 20%, X7R, 1206", Cap_Case=1206, Manufacturer=Kemet, Supplier Part Number 1=399-1248-1-ND, TempCo=X7R, Tolerance_%=20%, Value1="0.059 ohm", Value2=50V, ValueDisplayed=0.1uF
C21: library part CMP-0080102-1, "CAP, CERM, 0.22 µF, 16 V,+/- 10%, X7R, AEC-Q200 Grade 1, 0603", Cap_Case=0603, Manufacturer=Samsung, Supplier Part Number 1=1276-6868-1-ND, TempCo=X7R, Tolerance_%=10%, Value2=16V, ValueDisplayed=0.22µF
C22: library part CMP-0007634-2, "CAP, CERM, 1 uF, 50 V, +/- 10%, X7R, 0805", Cap_Case=0805, Manufacturer=AVX, Supplier Part Number 1=478-7956-1-ND, TempCo=X7R, Tolerance_%=10%, Value1=Unknown, Value2=50V, ValueDisplayed=1uF
C24: library part CMP-0007198-4, "CAP, CERM, 2200 pF, 50 V, +/- 5%, C0G/NP0, 0603", Cap_Case=0603, Manufacturer=MuRata, Supplier Part Number 1=490-1459-1-ND, TempCo=C0G/NP0, Tolerance_%=5%, Value1=Unknown, Value2=50V, ValueDisplayed=2200pF
C25: library part CMP-0011179-2, "CAP, AL, 22 uF, 50 V, +/- 20%, 0.88 ohm, AEC-Q200 Grade 2, SMD", Cap_Case=D, Manufacturer=Panasonic, Supplier Part Number 1=PCE3811CT-ND, Tolerance_%=20%, Value1="0.88 ohm", Value2=50V, ValueDisplayed=22uF
C26 C27: library part CMP-0007443-4, "CAP, CERM, 2200 pF, 50 V, +/- 10%, X7R, 0603", Cap_Case=0603, Manufacturer=MuRata, Supplier Part Number 1=490-1500-1-ND, TempCo=X7R, Tolerance_%=10%, Value1=Unknown, Value2=50V, ValueDisplayed=2200pF
D1: library part CMP-0002947-2, "LED, Red, SMD", Color=Red, Manufacturer="Wurth Elektronik", Power_TotalModule=72mW, Supplier Part Number 1=732-4978-1-ND, Value1=0.072W, Value2=2V
D2: library part CMP-0028431-1, "Diode, Schottky, 40 V, 5 A, SMC", Manufacturer="Diodes Inc.", Supplier Part Number 1=B540C-FDICT-ND, Value1=5A, Value2=0.55V
J1: library part CMP-0055534-1, "Header (Shrouded), 5.08 mm, 2x1, Tin, R/A, TH", Manufacturer="Phoenix Contact", Supplier Part Number 1=277-1106-ND
J2: library part CMP-0055294-1, "Connector, Plug, USB Type A, R/A, Top Mount SMT", Manufacturer=Molex, Supplier Part Number 1=WM17118-ND
J3: library part CMP-0055109-1, "Connector, Receptacle, USB TYPE A, R/A, Top Mount SMT", Color=Silver, Current_A=1A, Manufacturer=Mill-Max, Supplier Part Number 1=ED90065-ND, Voltage_V=30V
L1: library part CMP-0003170-1, "Ferrite Bead, 880 ohm @ 100 MHz, 4 A, 1812", Manufacturer="Wurth Elektronik", Value1="0.035 ohm", Value2=4A, ValueDisplayed="880 ohm"
L2 L6: library part CMP-0003170-1, "Ferrite Bead, 880 ohm @ 100 MHz, 4 A, 1812", Manufacturer="Wurth Elektronik", PartNumber=74279252, Value1="0.035 ohm", Value2=4A, ValueDisplayed="880 ohm"
L3: library part CMP-0061010-1, "Inductor, Shielded, Composite, 8.2 uH, 5.6 A, 0.03 ohm, SMD", Manufacturer=Coilcraft, Value1="0.03 ohm", Value2=5.6A, ValueDisplayed=8.2uH
L4: library part CMP-0082088-1, "Inductor, Shielded, CAPPR7.5-16X20, 1 µH, 11.1 A, 0.0094 ohm, AEC-Q200 Grade 1, SMD", Manufacturer=Coilcraft, Value1="0.0094 ohm", Value2=11.1A, ValueDisplayed=1µH
L5: library part CMP-0082088-1, "Inductor, Shielded, CAPPR7.5-16X20, 1 µH, 11.1 A, 0.0094 ohm, AEC-Q200 Grade 1, SMD", Manufacturer=Coilcraft, Value1="0.0094 ohm", Value2=11.1A, ValueDisplayed=NC
Logo3: library part CMP-0074847-1, "FCC_disclaimer"
Logo4: library part CMP-0074769-1
NT1: library part CMP-0078142-2, "Single point connection between nets.", Manufacturer=N/A
Q1: library part CMP-0000210-1, "MOSFET, 2-CH, N-CH, 20 V, 12 A, DPA0008A (VSON-8)", Alternate Manufacturer=None, Manufacturer="Texas Instruments", Supplier Part Number 1=296-37187-1-ND, Value1=0.01, Value2="11.7 nC"
R1: library part CMP-0022447-4, "RES, 49.9 k, 1%, 0.1 W, AEC-Q200 Grade 0, 0603", Manufacturer=Vishay-Dale, Power_W=100mW, Supplier Part Number 1=541-49.9KHCT-ND, TempCo="100 ppm/C", Tolerance_%=1%, Value2=0.1W, Value_Code=49k9, ValueDisplayed=49.9k
R2 R8: library part CMP-0025719-4, "RES, 15 k, 5%, 0.1 W, AEC-Q200 Grade 0, 0603", Manufacturer=Vishay-Dale, Power_W=100mW, Supplier Part Number 1=541-15KGCT-ND, TempCo="200 ppm/C", Tolerance_%=5%, Value2=0.1W, Value_Code=15k0, ValueDisplayed=15k
R3: library part CMP-0022732-2, "RES, 2.00, 1%, 0.125 W, 0603", Manufacturer=Vishay/Beyschlag, Power_W=125mW, Supplier Part Number 1=MCT06030C2008FP500-ND, TempCo="50 ppm/C", Tolerance_%=1%, Value2=0.125W, Value_Code=2R00, ValueDisplayed=2.00
R4: library part CMP-0016558-2, "RES, 0.015, 1%, 0.5 W, 2010", Manufacturer=Vishay-Dale, Power_W=500mW, Supplier Part Number 1=WSLE-.015CT-ND, TempCo="75 ppm/C", Tolerance_%=1%, Value2=0.5W, Value_Code=R015, ValueDisplayed=0.015
R5: library part CMP-0025753-4, "RES, 20 k, 5%, 0.1 W, AEC-Q200 Grade 0, 0603", Manufacturer=Vishay-Dale, Power_W=100mW, Supplier Part Number 1=541-20KGCT-ND, TempCo="200 ppm/C", Tolerance_%=5%, Value2=0.1W, Value_Code=20k0, ValueDisplayed=20k
R6: library part CMP-0022321-5, "RES, 301, 1%, 0.1 W, AEC-Q200 Grade 0, 0603", Manufacturer=Vishay-Dale, Power_W=100mW, Supplier Part Number 1=541-301HCT-ND, TempCo="100 ppm/C", Tolerance_%=1%, Value2=0.1W, Value_Code=301R, ValueDisplayed=300R
R7 R15: library part CMP-0021989-3, "RES, 4.99 k, 1%, 0.1 W, 0603", Manufacturer=Bourns, Power_W=100mW, Supplier Part Number 1=CR0603-FX-4991ELFTR-ND, TempCo="100 ppm/C", Tolerance_%=1%, Value2=0.1W, Value_Code=4k99, ValueDisplayed=4.99k
R9: library part CMP-0025701-4, "RES, 10 k, 5%, 0.1 W, AEC-Q200 Grade 0, 0603", Manufacturer=Vishay-Dale, Power_W=100mW, Supplier Part Number 1=541-10KGCT-ND, TempCo="200 ppm/C", Tolerance_%=5%, Value2=0.1W, Value_Code=10k0, ValueDisplayed=NC
R10: library part CMP-0020618-3, "RES, 100, 5%, 0.125 W, AEC-Q200 Grade 0, 0805", Manufacturer=Panasonic, Power_W=125mW, Supplier Part Number 1=P100ACT-ND, TempCo="200 ppm/C", Tolerance_%=5%, Value2=0.125W, Value_Code=100R, ValueDisplayed=100
R11: library part CMP-0022109-5, "RES, 1.00 k, 1%, 0.1 W, AEC-Q200 Grade 0, 0603", Manufacturer=Vishay-Dale, Power_W=100mW, Supplier Part Number 1=541-1.00KHCT-ND, TempCo="100 ppm/C", Tolerance_%=1%, Value2=0.1W, Value_Code=1k00, ValueDisplayed=NC
R12: library part CMP-0023343-3, "RES, 0, 1%, 0.1 W, AEC-Q200 Grade 0, 0603", Manufacturer="Stackpole Electronics Inc", Power_W=100mW, Supplier Part Number 1=RMCF0603ZT0R00CT-ND, TempCo=ppm/C, Tolerance_%=1%, Value2=0.1W, Value_Code=0, ValueDisplayed=0R
R13: library part CMP-0018759-2, "RES, 0, 5%, 0.25 W, 1206", Manufacturer="Yageo America", Power_W=250mW, Supplier Part Number 1=311-0.0ERCT-ND, TempCo="200 ppm/C", Tolerance_%=5%, Value2=0.25W, Value_Code=0000, ValueDisplayed=0
R14: library part CMP-0022513-4, "RES, 5.62 k, 1%, 0.1 W, AEC-Q200 Grade 0, 0603", Manufacturer=Vishay-Dale, Power_W=100mW, Supplier Part Number 1=541-5.62KHCT-ND, TempCo="100 ppm/C", Tolerance_%=1%, Value2=0.1W, Value_Code=5k62, ValueDisplayed=5.62k
R16 R17: library part CMP-0021990-4, "RES, 100 k, 1%, 0.1 W, AEC-Q200 Grade 0, 0603", Manufacturer=Vishay-Dale, Power_W=100mW, Supplier Part Number 1=541-100KHCT-ND, TempCo="100 ppm/C", Tolerance_%=1%, Value2=0.1W, Value_Code=100k
R18: library part CMP-0022369-4, "RES, 39.2 k, 1%, 0.1 W, AEC-Q200 Grade 0, 0603", Manufacturer=Vishay-Dale, Power_W=100mW, Supplier Part Number 1=541-39.2KHCT-ND, TempCo="100 ppm/C", Tolerance_%=1%, Value2=0.1W, Value_Code=39k2, ValueDisplayed=NC
R25: library part CMP-0025830-4, "RES, 5.1 k, 5%, 0.1 W, AEC-Q200 Grade 0, 0603", Manufacturer=Vishay-Dale, Power_W=100mW, Supplier Part Number 1=541-5.1KGCT-ND, TempCo="200 ppm/C", Tolerance_%=5%, Value2=0.1W, Value_Code=5k10, ValueDisplayed=5.1k
RT1: library part CMP-0002545-3, "Thermistor NTC, 470k ohm, 5%, 0603", Manufacturer=MuRata, Power_W=100mW, Supplier Part Number 1=490-2433-1-ND, Tolerance_%=5%
U1: library part CMP-0082640-2, "USB Type-A BC1.2 5-V 3.5-A Output, 36-V Input Synchronous Buck With Cable Compensation, RHB0032R (VQFN-32)", Alternate Manufacturer="Texas Instruments", Operating Temperature Range="-40 to 125 C", PartNumber=TPS25846QWRHBTQ1, Rating=Automotive

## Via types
v1: diameter 0.864, hole 0.406, Top Layer to Bottom Layer, 56 vias
v2: diameter 0.508, hole 0.33, Top Layer to Bottom Layer, 14 vias
v3: diameter 0.5, hole 0.2, Top Layer to Bottom Layer, 12 vias

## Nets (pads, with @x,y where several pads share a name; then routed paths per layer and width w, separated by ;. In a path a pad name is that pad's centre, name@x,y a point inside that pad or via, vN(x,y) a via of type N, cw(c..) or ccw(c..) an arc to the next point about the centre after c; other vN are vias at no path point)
/FAULT: U1.24
AGND: C21.2 NT1.2 R1.1 R7.1 R14.1 R15.2 R18.1 R25.1 U1.16 | length 47
  Top Layer w0.254: R1.1@11.55,23.633 11.55,22.075 11.575,22.05 R14.1@11.575,21.25 ; C21.2@11.575,16.225 10.65,16.225 10.4,16.475 10.4,20.375 10.859,20.834 R14.1@11.575,20.834 ; 11.609,21.65 v2(12,21.65) ; v2(14.65,29.875) R7.1@15.449,29.875 ; v2(15.825,18.1) 15.775,18.15 15.775,19.2 16.145,19.57 NT1.2@16.585,19.57
  Signal Layer 2 w0.254: v2(12,21.65) 12.875,21.65 15.825,18.7 v2(15.825,18.1) 20.425,13.5 v2(21.298,13.5) 20.15,14.648 20.15,16.875 19.625,17.4 18.379,17.4 15.05,20.729 15.05,26.8 15.425,27.175 15.425,28.45 14.65,29.225 v2(14.65,29.875)
  Bottom Layer w0.254: v2(12,21.65) 12.414,21.65 R18.1@13.239,22.475
CSN: C9.1 Q1.1 Q1.2 Q1.3 R4.2 R13.2 U1.13 | length 47.2
  Top Layer w0.254: v2(14.075,18.925) 13.549,18.925 C9.1@13.175,19.299 13.874,19.299 14.15,19.575 14.15,20.66 14.56,21.07 16.545,21.07 U1.13@16.55,21.075 ; v1(14.975,9.525) Q1.2@14.975,11.025 ; v2(27.7,7.125) 30.4,7.125 30.875,6.65 R4.2@30.875,5.15
  Top Layer w0.508: R13.2@15.65,8.125 R13.2@15.76,8.235
  Signal Layer 2 w0.254: v2(14.075,18.925) 20.025,12.975 27.15,12.975 28.257,11.868 28.257,7.536 27.847,7.125 v2(27.7,7.125)
  Signal Layer 2 w0.508: v1@16,9.525 20.012,5.513 20.05,5.55 v1@27.075,5.55
  other v1: 27.075,4.625 28.05,4.625 29.025,4.625 27.075,5.575 28.05,5.575 29.025,5.575 15.925,9.525 15.925,10.416 15.925,11.306 15.925,12.197 15.925,13.087
CSP: R6.1 U1.14 | length 5.8
  Top Layer w0.254: R6.1@13.175,17.762 14.387,17.762 14.7,18.075 14.7,20.3 14.97,20.57 U1.14@16.55,20.57
CTL1: R16.1 U1.5 | length 6.1
  Top Layer w0.254: R16.1@17.05,28.301 18.449,28.301 18.7,28.05 U1.5@18.7,23.72
CTL2: R17.1 U1.6 | length 3.9
  Top Layer w0.254: R17.1@17.05,26.725 17.825,26.725 18.2,26.35 U1.6@18.2,23.72
DATA_IN_N: J3.2 U1.17 | length 14
  Top Layer w0.254: J3.2@16.5,5.285 17.271,6.056 17.271,18.427 17.2,18.498 U1.17@17.2,18.925
DATA_IN_P: J3.3 U1.18 | length 14
  Top Layer w0.254: U1.18@17.7,18.925 17.7,18.645 17.729,18.616 17.729,6.056 J3.3@18.5,5.285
